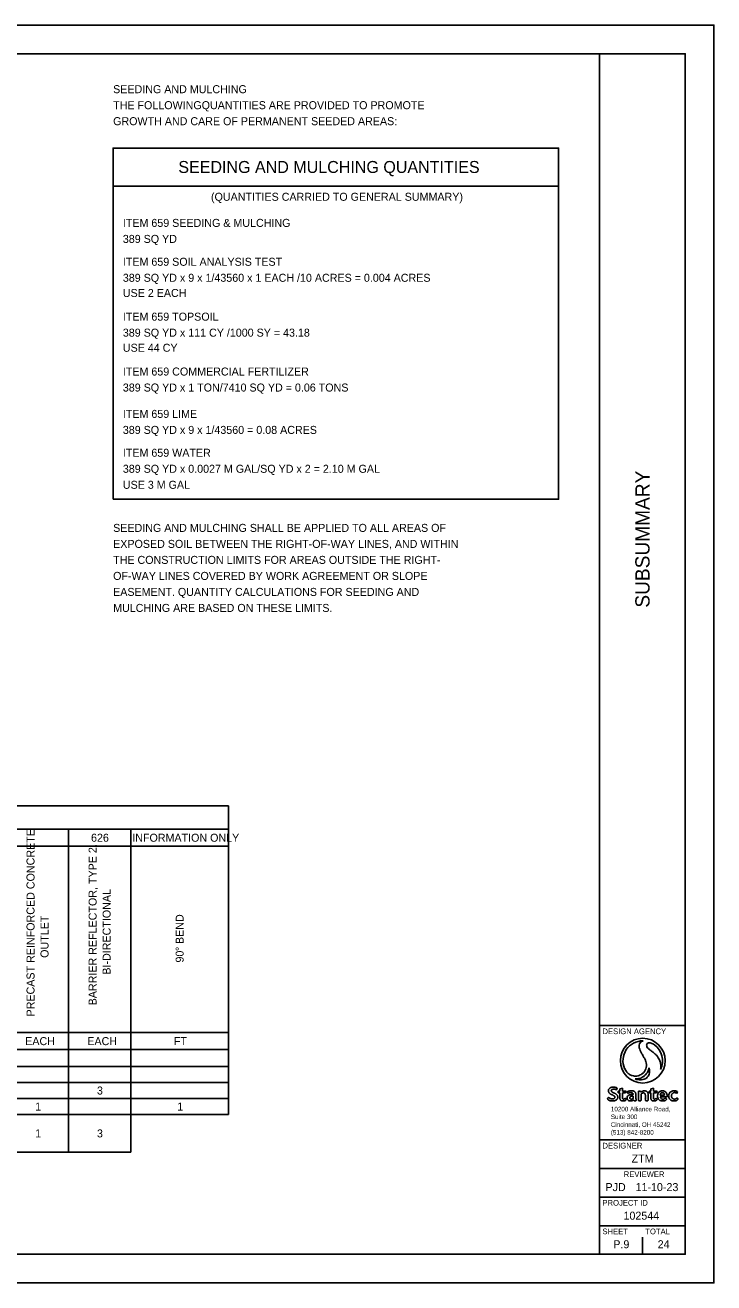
# Model space of a CAD drawing. Extents: x 0 to 34, y 0 to 22.
# Drawn here: x 21.94 to 34, y 0 to 22 of the extents above; entities that cross this region are included whole.
import ezdxf

# ---------------------------------------------------------------- set-up
doc = ezdxf.new("R2010")
doc.units = 0
for name, color, linetype in [('SH_Border', 7, 'Continuous'), ('SH_Cut_Line', 7, 'Continuous'), ('SH_Data', 7, 'Continuous'), ('SH_Text', 7, 'Continuous')]:
    doc.layers.add(name, color=color, linetype=linetype)

msp = doc.modelspace()

# ---------------------------------------------------------------- linework, layer by layer
at = {"layer": 'SH_Border'}
for p, q in [((32, 0.5), (32, 21.5)), ((32, 4.5), (33.5, 4.5)), ((32, 2.5), (33.5, 2.5)), ((32, 2), (33.5, 2)), ((32, 1.5), (33.5, 1.5)), ((32, 1), (33.5, 1))]:
    msp.add_line(p, q, dxfattribs=at)
msp.add_lwpolyline([(1.5, 21.5), (33.5, 21.5), (33.5, 0.5), (1.5, 0.5)], close=True, dxfattribs=at)
at = {"layer": 'SH_Cut_Line'}
msp.add_lwpolyline([(0, 0), (34, 0), (34, 22), (0, 22)], close=True, dxfattribs=at)
at = {"layer": 'SH_Data'}
for p, q in [((1.705, 8.346), (25.505, 8.346)), ((25.505, 8.346), (25.505, 2.944)), ((1.705, 7.934), (25.505, 7.934)), ((22.705, 7.934), (22.705, 2.285)), ((23.792, 7.934), (23.792, 2.285)), ((9.66, 7.638), (25.505, 7.638)), ((5.823, 4.377), (25.505, 4.377)), ((1.705, 4.08), (25.505, 4.08)), ((1.705, 3.784), (25.505, 3.784)), ((1.705, 3.504), (25.505, 3.504)), ((32.75, 3.5), (32.75, 3.5)), ((1.705, 3.224), (25.505, 3.224)), ((1.705, 2.944), (25.505, 2.944)), ((1.705, 2.285), (23.792, 2.285)), ((32.375, 0.675), (32.375, 0.675)), ((32.75, 0.5), (32.75, 0.8))]:
    msp.add_line(p, q, dxfattribs=at)
at = {"layer": 'SH_Text'}
for p, q in [((32.296, 3.376), (32.307, 3.41)), ((32.355, 3.354), (32.325, 3.354)), ((32.325, 3.354), (32.325, 3.321)), ((32.325, 3.321), (32.356, 3.321)), ((32.403, 3.407), (32.355, 3.394)), ((32.355, 3.394), (32.355, 3.354)), ((32.402, 3.237), (32.403, 3.321)), ((32.403, 3.354), (32.403, 3.407)), ((32.465, 3.354), (32.403, 3.354)), ((32.403, 3.321), (32.454, 3.321)), ((32.454, 3.321), (32.465, 3.354)), ((32.485, 3.343), (32.5, 3.315)), ((32.718, 3.355), (32.678, 3.355)), ((32.678, 3.355), (32.678, 3.202)), ((32.721, 3.335), (32.718, 3.355)), ((32.725, 3.202), (32.725, 3.303)), ((32.897, 3.354), (32.867, 3.354)), ((32.867, 3.354), (32.867, 3.321)), ((32.867, 3.321), (32.897, 3.321)), ((32.945, 3.407), (32.897, 3.394)), ((32.897, 3.394), (32.897, 3.354)), ((32.944, 3.237), (32.945, 3.321)), ((32.945, 3.354), (32.945, 3.407)), ((33.007, 3.354), (32.945, 3.354)), ((32.945, 3.321), (32.995, 3.321)), ((32.995, 3.321), (33.007, 3.354)), ((33.353, 3.314), (33.364, 3.345)), ((32.59, 3.265), (32.59, 3.227)), ((33.135, 3.283), (33.062, 3.283)), ((33.062, 3.254), (33.183, 3.254))]:
    msp.add_line(p, q, dxfattribs=at)
for points in [[(23.485, 19.186), (31.283, 19.186), (31.283, 19.851), (23.485, 19.851)], [(23.485, 13.707), (31.283, 13.707), (31.283, 19.186), (23.485, 19.186)]]:
    msp.add_lwpolyline(points, close=True, dxfattribs=at)
for points in [[(32.763, 4.233), (32.763, 4.233)], [(32.961, 4.165), (32.961, 4.165)]]:
    msp.add_lwpolyline(points, dxfattribs=at)
msp.add_circle((32.755, 3.887), 0.392, dxfattribs=at)
for start, end in [(88.7666, 203.6845), (88.7601, 88.7666), (333.7815, 53.4326), (247.1184, 251.458)]:
    msp.add_arc((32.755, 3.887), 0.346, start, end, dxfattribs=at)
for points, degree in [([(32.763, 4.233), (32.754, 4.231), (32.735, 4.227), (32.709, 4.201), (32.69, 4.158), (32.693, 4.109), (32.71, 4.063), (32.735, 4.017), (32.762, 3.967), (32.792, 3.92), (32.812, 3.872), (32.822, 3.82), (32.816, 3.767), (32.8, 3.719), (32.771, 3.676), (32.732, 3.645), (32.692, 3.627), (32.655, 3.615), (32.614, 3.615), (32.568, 3.622), (32.524, 3.642), (32.476, 3.683), (32.453, 3.723), (32.439, 3.748)], 3), ([(32.763, 4.233), (32.763, 4.233), (32.763, 4.233), (32.763, 4.233)], 2), ([(33.066, 3.734), (33.069, 3.746), (33.074, 3.769), (33.073, 3.806), (33.069, 3.838), (33.06, 3.868), (33.049, 3.902), (33.029, 3.939), (33.001, 3.975), (32.965, 4.012), (32.919, 4.045), (32.873, 4.083), (32.835, 4.111), (32.822, 4.145), (32.822, 4.17), (32.834, 4.187), (32.851, 4.199), (32.873, 4.201), (32.899, 4.196), (32.929, 4.183), (32.95, 4.171), (32.961, 4.165)], 3), ([(32.621, 3.568), (32.629, 3.567), (32.649, 3.566), (32.684, 3.572), (32.722, 3.581), (32.756, 3.601), (32.788, 3.623), (32.818, 3.655), (32.843, 3.691), (32.858, 3.728), (32.863, 3.75), (32.865, 3.76)], 3), ([(32.865, 3.76), (32.868, 3.752), (32.874, 3.729), (32.876, 3.692), (32.87, 3.651), (32.849, 3.614), (32.82, 3.58), (32.779, 3.561), (32.736, 3.551), (32.691, 3.55), (32.66, 3.556), (32.645, 3.559)], 3), ([(32.307, 3.41), (32.305, 3.411), (32.296, 3.415), (32.278, 3.42), (32.256, 3.423), (32.236, 3.424), (32.219, 3.422), (32.203, 3.419), (32.187, 3.413), (32.172, 3.403), (32.161, 3.389), (32.155, 3.375), (32.154, 3.362), (32.155, 3.35), (32.157, 3.339), (32.162, 3.329), (32.168, 3.321), (32.175, 3.313), (32.184, 3.306), (32.195, 3.3), (32.208, 3.293), (32.223, 3.286), (32.238, 3.28), (32.25, 3.273), (32.259, 3.266), (32.266, 3.258), (32.268, 3.249), (32.267, 3.241), (32.264, 3.231), (32.256, 3.224), (32.244, 3.218), (32.229, 3.216), (32.213, 3.217), (32.199, 3.22), (32.187, 3.226), (32.178, 3.23), (32.172, 3.235), (32.166, 3.238), (32.16, 3.24), (32.154, 3.24), (32.148, 3.238), (32.143, 3.234), (32.14, 3.227), (32.14, 3.221), (32.141, 3.214), (32.146, 3.207), (32.156, 3.197), (32.174, 3.188), (32.197, 3.182), (32.219, 3.181), (32.239, 3.181), (32.256, 3.183), (32.271, 3.188), (32.286, 3.195), (32.301, 3.207), (32.313, 3.221), (32.318, 3.238), (32.318, 3.254), (32.316, 3.268), (32.311, 3.279), (32.304, 3.29), (32.293, 3.3), (32.279, 3.309), (32.265, 3.316), (32.249, 3.323), (32.233, 3.33), (32.219, 3.338), (32.209, 3.346), (32.205, 3.354), (32.205, 3.363), (32.207, 3.371), (32.212, 3.378), (32.22, 3.383), (32.23, 3.386), (32.242, 3.387), (32.253, 3.387), (32.265, 3.385), (32.276, 3.383), (32.286, 3.38), (32.293, 3.377), (32.296, 3.376)], 3), ([(32.356, 3.321), (32.355, 3.291), (32.355, 3.26), (32.356, 3.225), (32.357, 3.216), (32.36, 3.205), (32.367, 3.197), (32.374, 3.191), (32.381, 3.186), (32.392, 3.182), (32.407, 3.181), (32.423, 3.181), (32.439, 3.183), (32.451, 3.189), (32.46, 3.197), (32.464, 3.205), (32.464, 3.212), (32.463, 3.218), (32.46, 3.222), (32.456, 3.224), (32.451, 3.225), (32.447, 3.225), (32.442, 3.224), (32.438, 3.22), (32.433, 3.217), (32.427, 3.214), (32.42, 3.212), (32.414, 3.213), (32.408, 3.216), (32.404, 3.22), (32.402, 3.228), (32.402, 3.233), (32.402, 3.237)], 3), ([(32.595, 3.203), (32.595, 3.202), (32.595, 3.198), (32.599, 3.192), (32.605, 3.185), (32.615, 3.181), (32.626, 3.181), (32.636, 3.183), (32.64, 3.191), (32.64, 3.199), (32.637, 3.21), (32.635, 3.239), (32.637, 3.27), (32.636, 3.303), (32.632, 3.32), (32.623, 3.334), (32.613, 3.345), (32.597, 3.354), (32.577, 3.359), (32.553, 3.36), (32.529, 3.358), (32.506, 3.353), (32.492, 3.346), (32.485, 3.343)], 3), ([(32.5, 3.315), (32.502, 3.316), (32.509, 3.32), (32.519, 3.323), (32.533, 3.326), (32.545, 3.327), (32.558, 3.327), (32.57, 3.323), (32.58, 3.317), (32.587, 3.309), (32.59, 3.3), (32.59, 3.295), (32.59, 3.293)], 3), ([(32.725, 3.303), (32.726, 3.304), (32.729, 3.307), (32.737, 3.311), (32.747, 3.318), (32.76, 3.322), (32.773, 3.322), (32.786, 3.318), (32.795, 3.309), (32.799, 3.298), (32.802, 3.283), (32.8, 3.262), (32.801, 3.234), (32.8, 3.211), (32.801, 3.195), (32.806, 3.187), (32.816, 3.181), (32.827, 3.181), (32.838, 3.183), (32.846, 3.19), (32.849, 3.202), (32.847, 3.225), (32.848, 3.252), (32.847, 3.282), (32.849, 3.301), (32.846, 3.318), (32.841, 3.329), (32.832, 3.341), (32.819, 3.351), (32.802, 3.359), (32.783, 3.359), (32.766, 3.358), (32.751, 3.353), (32.737, 3.347), (32.728, 3.339), (32.723, 3.336), (32.721, 3.335)], 3), ([(32.897, 3.321), (32.897, 3.291), (32.897, 3.26), (32.897, 3.225), (32.899, 3.216), (32.902, 3.205), (32.909, 3.197), (32.915, 3.191), (32.922, 3.186), (32.934, 3.182), (32.949, 3.181), (32.965, 3.181), (32.981, 3.183), (32.993, 3.189), (33.001, 3.197), (33.006, 3.205), (33.006, 3.212), (33.005, 3.218), (33.002, 3.222), (32.998, 3.224), (32.993, 3.225), (32.989, 3.225), (32.984, 3.224), (32.979, 3.22), (32.975, 3.217), (32.969, 3.214), (32.962, 3.212), (32.956, 3.213), (32.95, 3.216), (32.946, 3.22), (32.944, 3.228), (32.944, 3.233), (32.944, 3.237)], 3), ([(33.183, 3.254), (33.183, 3.258), (33.184, 3.27), (33.182, 3.289), (33.177, 3.31), (33.167, 3.326), (33.156, 3.34), (33.141, 3.35), (33.123, 3.357), (33.102, 3.359), (33.082, 3.358), (33.063, 3.352), (33.046, 3.343), (33.032, 3.329), (33.022, 3.313), (33.017, 3.295), (33.014, 3.276), (33.014, 3.256), (33.019, 3.238), (33.026, 3.22), (33.037, 3.204), (33.054, 3.192), (33.075, 3.182), (33.1, 3.181), (33.122, 3.181), (33.141, 3.185), (33.156, 3.192), (33.167, 3.201), (33.171, 3.212), (33.169, 3.22), (33.165, 3.227), (33.158, 3.229), (33.152, 3.229), (33.144, 3.227), (33.135, 3.222), (33.125, 3.215), (33.113, 3.213), (33.101, 3.212), (33.09, 3.215), (33.081, 3.222), (33.071, 3.229), (33.066, 3.239), (33.063, 3.248), (33.062, 3.252), (33.062, 3.254)], 3), ([(33.062, 3.283), (33.062, 3.285), (33.062, 3.288), (33.062, 3.296), (33.064, 3.305), (33.07, 3.314), (33.079, 3.322), (33.091, 3.326), (33.104, 3.327), (33.116, 3.323), (33.126, 3.316), (33.132, 3.305), (33.134, 3.294), (33.135, 3.287), (33.135, 3.283)], 3), ([(33.364, 3.345), (33.36, 3.348), (33.35, 3.353), (33.33, 3.358), (33.306, 3.361), (33.28, 3.358), (33.256, 3.35), (33.235, 3.336), (33.22, 3.318), (33.211, 3.296), (33.208, 3.272), (33.21, 3.248), (33.218, 3.227), (33.23, 3.21), (33.247, 3.196), (33.271, 3.185), (33.298, 3.181), (33.323, 3.182), (33.344, 3.188), (33.36, 3.195), (33.371, 3.205), (33.371, 3.215), (33.37, 3.222), (33.365, 3.227), (33.36, 3.23), (33.355, 3.23), (33.347, 3.229), (33.341, 3.223), (33.331, 3.219), (33.321, 3.215), (33.307, 3.214), (33.293, 3.215), (33.279, 3.222), (33.268, 3.233), (33.26, 3.246), (33.257, 3.261), (33.255, 3.275), (33.259, 3.29), (33.265, 3.303), (33.273, 3.314), (33.285, 3.322), (33.297, 3.327), (33.312, 3.328), (33.327, 3.327), (33.342, 3.322), (33.349, 3.317), (33.353, 3.314)], 3), ([(32.59, 3.293), (32.587, 3.293), (32.577, 3.293), (32.559, 3.292), (32.539, 3.291), (32.519, 3.287), (32.501, 3.279), (32.486, 3.266), (32.479, 3.247), (32.48, 3.229), (32.482, 3.214), (32.492, 3.201), (32.505, 3.189), (32.525, 3.182), (32.545, 3.181), (32.563, 3.184), (32.577, 3.189), (32.588, 3.196), (32.592, 3.201), (32.595, 3.203)], 3), ([(32.59, 3.227), (32.589, 3.226), (32.584, 3.223), (32.576, 3.218), (32.565, 3.214), (32.553, 3.213), (32.542, 3.216), (32.535, 3.22), (32.53, 3.226), (32.527, 3.233), (32.527, 3.24), (32.528, 3.247), (32.532, 3.254), (32.54, 3.258), (32.548, 3.262), (32.56, 3.264), (32.572, 3.264), (32.582, 3.265), (32.588, 3.265), (32.59, 3.265)], 3), ([(32.678, 3.202), (32.679, 3.2), (32.68, 3.195), (32.683, 3.188), (32.692, 3.181), (32.703, 3.181), (32.715, 3.182), (32.723, 3.19), (32.725, 3.197), (32.725, 3.2), (32.725, 3.202)], 3)]:
    msp.add_open_spline(points, degree=degree, dxfattribs=at)

# ---------------------------------------------------------------- texts
at = {"layer": 'SH_Data'}
msp.add_text('SUBSUMMARY', height=0.25, rotation=90, dxfattribs=at).set_placement((32.875, 11.811))
for s, height, p in [('DESIGN AGENCY', 0.1, (32.05, 4.35)), ('DESIGNER', 0.1, (32.05, 2.35)), ('ZTM', 0.14, (32.56, 2.105)), ('REVIEWER', 0.1, (32.422, 1.85)), ('PJD', 0.14, (32.103, 1.605)), ('11-10-23', 0.14, (32.629, 1.605)), ('PROJECT ID', 0.1, (32.05, 1.35)), ('102544', 0.14, (32.418, 1.105)), ('SHEET', 0.1, (32.05, 0.85)), ('TOTAL', 0.1, (32.8, 0.85)), ('P.9', 0.14, (32.24, 0.605)), ('24', 0.14, (33.016, 0.605))]:
    msp.add_text(s, height=height, dxfattribs=at).set_placement(p)
at = {"layer": 'SH_Text'}
for s, height, p in [('SEEDING AND MULCHING', 0.14, (23.485, 20.81)), ('THE FOLLOWINGQUANTITIES ARE PROVIDED TO PROMOTE', 0.14, (23.485, 20.53)), ('GROWTH AND CARE OF PERMANENT SEEDED AREAS:', 0.14, (23.485, 20.25)), ('SEEDING AND MULCHING QUANTITIES', 0.21, (24.626, 19.414)), ('(QUANTITIES CARRIED TO GENERAL SUMMARY)', 0.14, (25.198, 18.928)), ('ITEM 659 SEEDING & MULCHING', 0.14, (23.655, 18.471)), ('389 SQ YD', 0.14, (23.655, 18.191)), ('ITEM 659 SOIL ANALYSIS TEST', 0.14, (23.655, 17.791)), ('389 SQ YD x 9 x 1/43560 x 1 EACH /10 ACRES = 0.004 ACRES', 0.14, (23.655, 17.511)), ('USE 2 EACH', 0.14, (23.655, 17.245)), ('ITEM 659 TOPSOIL', 0.14, (23.655, 16.831)), ('389 SQ YD x 111 CY /1000 SY = 43.18', 0.14, (23.655, 16.551)), ('USE 44 CY', 0.14, (23.655, 16.287)), ('ITEM 659 COMMERCIAL FERTILIZER', 0.14, (23.655, 15.871)), ('389 SQ YD x 1 TON/7410 SQ YD = 0.06 TONS', 0.14, (23.655, 15.591)), ('ITEM 659 LIME', 0.14, (23.655, 15.13)), ('389 SQ YD x 9 x 1/43560 = 0.08 ACRES', 0.14, (23.655, 14.85)), ('ITEM 659 WATER', 0.14, (23.655, 14.45)), ('389 SQ YD x 0.0027 M GAL/SQ YD x 2 = 2.10 M GAL', 0.14, (23.655, 14.17)), ('USE 3 M GAL', 0.14, (23.655, 13.89)), ('SEEDING AND MULCHING SHALL BE APPLIED TO ALL AREAS OF', 0.14, (23.485, 13.136)), ('EXPOSED SOIL BETWEEN THE RIGHT-OF-WAY LINES, AND WITHIN', 0.14, (23.485, 12.856)), ('THE CONSTRUCTION LIMITS FOR AREAS OUTSIDE THE RIGHT-', 0.14, (23.485, 12.576)), ('OF-WAY LINES COVERED BY WORK AGREEMENT OR SLOPE', 0.14, (23.485, 12.296)), ('EASEMENT. QUANTITY CALCULATIONS FOR SEEDING AND', 0.14, (23.485, 12.016)), ('MULCHING ARE BASED ON THESE LIMITS.', 0.14, (23.485, 11.736)), ('626', 0.14, (23.098, 7.716)), ('INFORMATION ONLY', 0.14, (23.82, 7.716)), ('EACH', 0.14, (21.946, 4.158)), ('EACH', 0.14, (23.033, 4.158)), ('FT', 0.14, (24.548, 4.158)), ('3', 0.14, (23.202, 3.294)), ('1', 0.14, (22.12, 3.014)), ('1', 0.14, (24.607, 3.014)), ('1', 0.14, (22.12, 2.544)), ('3', 0.14, (23.202, 2.544))]:
    msp.add_text(s, height=height, dxfattribs=at).set_placement(p)
for s, height, rotation, p in [('PRECAST REINFORCED CONCRETE ', 0.14, 90, (22.109, 4.66)), ('BARRIER REFLECTOR, TYPE 2,', 0.14, 90, (23.196, 4.854)), (' BI-DIRECTIONAL', 0.14, 90, (23.441, 5.339)), ('OUTLET', 0.14, 90, (22.354, 5.685)), (' BEND ', 0.14, 90, (24.719, 5.875)), ('°', 0.14, 90, (24.719, 5.804)), ('90', 0.14, 90, (24.719, 5.603)), ('10200 Alliance Road,', 0.07948, 360, (32.197, 3)), ('Suite 300', 0.0795, 360, (32.197, 2.865)), ('Cincinnati, OH 45242', 0.07948, 360, (32.197, 2.729)), ('(513) 842-8200', 0.07948, 360, (32.197, 2.593))]:
    msp.add_text(s, height=height, rotation=rotation, dxfattribs=at).set_placement(p)

doc.saveas('drawing.dxf')
